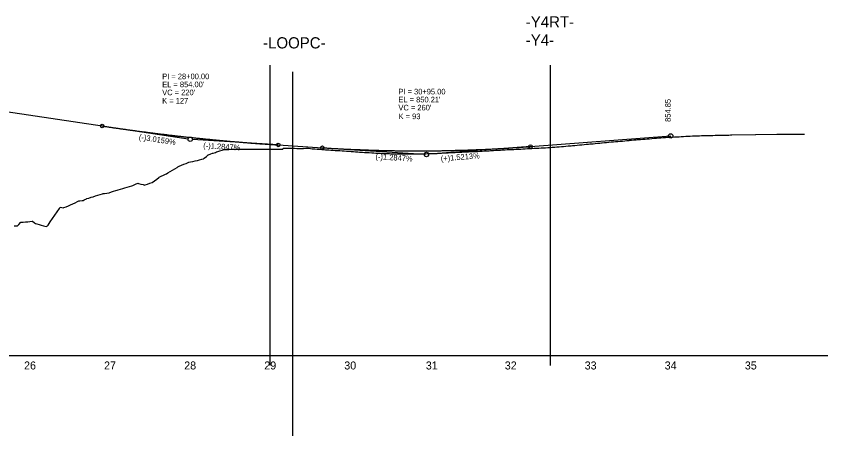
# Model space of a CAD drawing. Extents: x 570622 to 580296, y -55533 to -48575.
# Drawn here: x 575380 to 576394, y -53536 to -53012 of the extents above; entities that cross this region are included whole.
import ezdxf

# ---------------------------------------------------------------- set-up
doc = ezdxf.new("R2010")
doc.units = 0
for name, color, linetype in [('Default', 7, 'Continuous'), ('Exist Profile Cell', 7, 'Continuous'), ('Exist Vertical Profile Ground Line', 7, 'Continuous'), ('Exist Vertical Profile Horizontal Axis Label Major', 7, 'Continuous'), ('Prop Vertical Profile Curve Label', 7, 'Continuous'), ('Prop Vertical Profile Grade', 7, 'Continuous'), ('Prop Vertical Profile Grade Label', 7, 'Continuous'), ('Prop VPI Label', 7, 'Continuous')]:
    doc.layers.add(name, color=color, linetype=linetype)

msp = doc.modelspace()

# ---------------------------------------------------------------- linework, layer by layer
at = {"layer": 'Default'}
for p, q in [((575697.6, -53447.9), (575697.6, -53072.8)), ((576047.6, -53447.9), (576047.6, -53072.8)), ((575725.7, -53535.7), (575725.7, -53081.3)), ((576147.6, -53165.3), (576147.6, -53165.3)), ((576197.6, -53161.4), (576197.6, -53161.4)), ((576047.6, -53173.3), (576047.6, -53173.3)), ((576097.6, -53169.9), (576097.6, -53169.9)), ((575947.6, -53179.4), (575947.6, -53179.4)), ((575997.6, -53176.8), (575997.6, -53176.8))]:
    msp.add_line(p, q, dxfattribs=at)
at = {"layer": 'Exist Profile Cell'}
msp.add_line((573797.6, -53435.4), (576393.8, -53435.4), dxfattribs=at)
at = {"layer": 'Exist Vertical Profile Ground Line'}
for points in [[(576040.7, -53176.1), (576041.3, -53176), (576044.2, -53175.8), (576047, -53175.6), (576049.8, -53175.4), (576052.8, -53175.2), (576055.5, -53175), (576058.3, -53174.8), (576061.1, -53174.5), (576063.9, -53174.3), (576066.8, -53174), (576069.6, -53173.8), (576072.4, -53173.6), (576073.3, -53173.5), (576075.2, -53173.3), (576076.1, -53173.2), (576078.1, -53173), (576080.9, -53172.8), (576083.7, -53172.5), (576086.5, -53172.2), (576089.4, -53171.9), (576092.2, -53171.7), (576093.3, -53171.6), (576095, -53171.4), (576096.6, -53171.3), (576097.8, -53171.2), (576100.6, -53171), (576103.5, -53170.7), (576106.3, -53170.4), (576109.1, -53170.2), (576111.3, -53169.9), (576111.9, -53169.9), (576114.8, -53169.6), (576117.6, -53169.3), (576120.4, -53169), (576123.2, -53168.8), (576124.1, -53168.7), (576126.1, -53168.5), (576128.9, -53168.3), (576131.7, -53168.1), (576134.5, -53167.8), (576135.1, -53167.8), (576137.4, -53167.6), (576140.2, -53167.3), (576143, -53167), (576145.8, -53166.8), (576146.3, -53166.7), (576148.7, -53166.5), (576151.5, -53166.3), (576153, -53166.2), (576154.3, -53166.1), (576155.7, -53165.9), (576157.1, -53165.8), (576159.9, -53165.6), (576162.8, -53165.4), (576163.5, -53165.3), (576165.6, -53165.2), (576168.4, -53164.9), (576171.2, -53164.7), (576174.1, -53164.5), (576177.1, -53164.2), (576179.7, -53164), (576182.5, -53163.8), (576185.4, -53163.6), (576188.2, -53163.4), (576191, -53163.1), (576193.8, -53162.9), (576194.3, -53162.9), (576196.7, -53162.8), (576197.7, -53162.7), (576199.5, -53162.6), (576202.3, -53162.5), (576205.1, -53162.3), (576208, -53162.2), (576210.8, -53162), (576213.6, -53161.9), (576216.4, -53161.7), (576219.2, -53161.6), (576221.5, -53161.5), (576222.1, -53161.4), (576224.9, -53161.2), (576227, -53161.1), (576227.7, -53161.1), (576230.8, -53161), (576233.4, -53161), (576236.2, -53160.9), (576239, -53160.8), (576241.8, -53160.8), (576244.7, -53160.7), (576247.5, -53160.6), (576248.9, -53160.6), (576250.3, -53160.6), (576253.1, -53160.5), (576256, -53160.4), (576258.8, -53160.4), (576261.6, -53160.3), (576264.4, -53160.2), (576267.3, -53160.2), (576270.1, -53160.1), (576272.5, -53160), (576272.9, -53160)], [(576272.9, -53160), (576273.4, -53160), (576274, -53160), (576303.4, -53159.4), (576304.1, -53159.4), (576330.1, -53158.9), (576331.2, -53158.9), (576360.2, -53159.1), (576364.6, -53159.2)], [(575809.8, -53181.4), (575812.6, -53181.6), (575815.4, -53181.8), (575818.3, -53181.9), (575821.1, -53182.1), (575824.2, -53182.3), (575826.7, -53182.5), (575829.6, -53182.6), (575832.4, -53182.8), (575835.2, -53182.9), (575837.4, -53183), (575838, -53183.1), (575838.7, -53183.1), (575839.1, -53183.1), (575840.9, -53183.2), (575843.7, -53183.2), (575846.5, -53183.3), (575849.3, -53183.4), (575852.2, -53183.5), (575855, -53183.6), (575857.8, -53183.6), (575859.2, -53183.7), (575860.6, -53183.7), (575863.5, -53183.7), (575866.3, -53183.7), (575869.1, -53183.7), (575871.9, -53183.7), (575874.7, -53183.7), (575877.6, -53183.7), (575879.6, -53183.7), (575880.4, -53183.6), (575883.2, -53183.6), (575886, -53183.5), (575886.9, -53183.5), (575888.9, -53183.4), (575891.7, -53183.4), (575894.5, -53183.3), (575895.6, -53183.3), (575897.3, -53183.2), (575900.2, -53183.1), (575903, -53183), (575905.8, -53183), (575906.7, -53182.9), (575908.6, -53182.8), (575911.5, -53182.7), (575914.3, -53182.5), (575917.1, -53182.4), (575919, -53182.3), (575919.9, -53182.2), (575922.7, -53182.1), (575925.6, -53182), (575928.4, -53181.9), (575931.2, -53181.7), (575934, -53181.6), (575936.9, -53181.4), (575939.7, -53181.3), (575942.5, -53181.1), (575943.3, -53181.1), (575945.3, -53181), (575948.2, -53180.9), (575951, -53180.7), (575953.2, -53180.6), (575953.8, -53180.6), (575956.6, -53180.5), (575959.5, -53180.3), (575962.3, -53180.1), (575965.1, -53180), (575967.9, -53179.8), (575969.1, -53179.8), (575970.8, -53179.7), (575972.8, -53179.6), (575973.6, -53179.5), (575976.4, -53179.4), (575979.2, -53179.2), (575982, -53179), (575984.9, -53178.9), (575987.7, -53178.7), (575990.5, -53178.6), (575991.1, -53178.5), (575993.3, -53178.4), (575993.9, -53178.4), (575996.2, -53178.3), (575996.9, -53178.2), (575999, -53178.1), (576001.8, -53178), (576004.6, -53177.8), (576007.5, -53177.7), (576010.3, -53177.6), (576013.1, -53177.4), (576014.8, -53177.3), (576015.9, -53177.3), (576018.8, -53177.1), (576021.6, -53177), (576024.4, -53176.9), (576027.2, -53176.7), (576030.1, -53176.6), (576032.9, -53176.4), (576035.7, -53176.3), (576036.9, -53176.3), (576038.5, -53176.2), (576040.7, -53176.1)], [(575586.7, -53197.8), (575589.5, -53196.7), (575592.4, -53195.5), (575595.2, -53194.3), (575595.9, -53194), (575598, -53193.6), (575600.8, -53193.1), (575603.7, -53192.5), (575606.5, -53191.8), (575609.3, -53191.1), (575612.1, -53190.3), (575614.3, -53189.7), (575615, -53189.2), (575617.8, -53186.9), (575619.9, -53185), (575620.6, -53184.8), (575623.4, -53183.8), (575625.6, -53182.9), (575626.2, -53182.7), (575629.1, -53181.8), (575630.6, -53181.3), (575631.9, -53180.9), (575634.7, -53180), (575637.5, -53179.1), (575640.4, -53178.2), (575640.9, -53178), (575643.2, -53178), (575646, -53178), (575648.8, -53177.9), (575650.9, -53177.9), (575651.7, -53177.9), (575654.5, -53177.9), (575654.9, -53177.9), (575657.3, -53177.9), (575660.1, -53177.9), (575663, -53177.9), (575665.8, -53177.8), (575668.6, -53177.8), (575671.4, -53177.8), (575674.3, -53177.7), (575677.1, -53177.7), (575679.9, -53177.6), (575680.8, -53177.6), (575682.7, -53177.6), (575685.5, -53177.7), (575688.4, -53177.7), (575691.2, -53177.7), (575693.3, -53177.8), (575694, -53177.8), (575696.8, -53177.8), (575699.7, -53177.7), (575702.5, -53177.7), (575703.8, -53177.7), (575705.3, -53177.7), (575708.1, -53177.7), (575711, -53177.7), (575713.4, -53177.7), (575713.8, -53176.4), (575716.6, -53176.5), (575719.4, -53176.5), (575722.3, -53176.6), (575725.1, -53176.7), (575727.9, -53176.7), (575730.7, -53176.8), (575733.6, -53176.9), (575736.4, -53176.9), (575737.5, -53176.9), (575738, -53176.9), (575739.2, -53177), (575742, -53176.7), (575743.7, -53176.6), (575744.8, -53176.7), (575747.7, -53177), (575750, -53177.2), (575750.5, -53177.2), (575753.3, -53177.5), (575756.1, -53177.7), (575759, -53177.9), (575761.8, -53178.1), (575764.6, -53178.4), (575766.7, -53178.5), (575767.4, -53178.6), (575770.3, -53178.8), (575770.7, -53178.8), (575773.1, -53179), (575775.9, -53179.1), (575778.7, -53179.3), (575781.6, -53179.5), (575784.4, -53179.6), (575787.2, -53179.8), (575789.5, -53180), (575790, -53180), (575792.9, -53180.2), (575795.7, -53180.4), (575798.5, -53180.6), (575800.4, -53180.8), (575801.3, -53180.8), (575804.1, -53181), (575807, -53181.2), (575809, -53181.4), (575809.8, -53181.4)], [(575377.8, -53273.5), (575380.6, -53273.6), (575381.9, -53273.6), (575383.4, -53272), (575386.2, -53269), (575389, -53268.8), (575391.9, -53268.6), (575394.7, -53268.4), (575397.5, -53268.1), (575400.3, -53267.9), (575400.7, -53267.9), (575403.2, -53269.6), (575404.4, -53270.5), (575406, -53271), (575408.8, -53271.8), (575411.6, -53272.6), (575414.5, -53273.4), (575417.5, -53274.2), (575419.5, -53273.4), (575420.1, -53272.5), (575422.9, -53268.4), (575425.8, -53264.3), (575428.6, -53260.2), (575431.4, -53256), (575434.2, -53251.8), (575435.2, -53250.4), (575437.1, -53250.7), (575439.6, -53251), (575439.9, -53250.8), (575442.7, -53249.6), (575445.5, -53248.4), (575448.3, -53247.2), (575451.2, -53245.9), (575454, -53244.6), (575456.8, -53243.2), (575458.3, -53242.5), (575459.6, -53242.3), (575462.5, -53241.9), (575463.8, -53241.7), (575465.3, -53241), (575468.1, -53239.6), (575468.5, -53239.4), (575470.9, -53238.8), (575473.8, -53237.9), (575476.6, -53237.1), (575479.4, -53236.2), (575482.2, -53235.3), (575485.1, -53234.4), (575487.9, -53233.5), (575488.8, -53233.2), (575490.7, -53233), (575493.5, -53232.7), (575496.4, -53232.3), (575499.2, -53231.2), (575501.6, -53230.3), (575502, -53230.2), (575504.8, -53229.4), (575506.2, -53229), (575507.6, -53228.6), (575510.5, -53227.8), (575513.3, -53227), (575516.1, -53226.1), (575518.9, -53225.2), (575521.8, -53224.4), (575524.6, -53223.4), (575525.8, -53223), (575527.4, -53222.4), (575530.2, -53221.2), (575532.5, -53220.3), (575533.1, -53220.5), (575535.9, -53221.3), (575538.7, -53222.1), (575540.6, -53222.6), (575541.5, -53222.3), (575544.4, -53221.3), (575547.2, -53220.3), (575550, -53219.2), (575552.8, -53217.2), (575555.7, -53215.2), (575558.5, -53213.1), (575559, -53212.7), (575561.3, -53211.7), (575564.1, -53210.4), (575566.9, -53209.1), (575568.1, -53208.6), (575569.8, -53207.5), (575572.6, -53205.8), (575575.4, -53204.1), (575578.2, -53202.3), (575581.1, -53200.5), (575582.2, -53199.7), (575583.6, -53199), (575583.9, -53198.9), (575586.7, -53197.8)]]:
    msp.add_lwpolyline(points, dxfattribs=at)
at = {"layer": 'Prop Vertical Profile Curve Label'}
for centre in [(575487.6, -53148.8), (575707.6, -53172.5), (575762.6, -53176), (576022.6, -53174.5)]:
    msp.add_circle(centre, 2.25, dxfattribs=at)
at = {"layer": 'Prop Vertical Profile Grade'}
for p, q in [((575367.6, -53130.7), (575487.6, -53148.8)), ((576022.6, -53174.5), (576197.6, -53161.2)), ((575707.6, -53172.5), (575762.6, -53176))]:
    msp.add_line(p, q, dxfattribs=at)
for points in [[(575487.6, -53148.8), (575492, -53149.5), (575496.4, -53150.1), (575500.8, -53150.8), (575505.2, -53151.4), (575509.6, -53152.1), (575514, -53152.7), (575518.4, -53153.3), (575522.8, -53153.9), (575527.2, -53154.5), (575531.6, -53155.1), (575536, -53155.7), (575540.4, -53156.2), (575544.8, -53156.8), (575549.2, -53157.4), (575553.6, -53157.9), (575558, -53158.5), (575562.4, -53159), (575566.8, -53159.5), (575571.2, -53160.1), (575575.6, -53160.6), (575580, -53161.1), (575584.4, -53161.6), (575588.8, -53162.1), (575593.2, -53162.6), (575597.6, -53163), (575602, -53163.5), (575606.4, -53164), (575610.8, -53164.4), (575615.2, -53164.9), (575619.6, -53165.3), (575624, -53165.7), (575628.4, -53166.2), (575632.8, -53166.6), (575637.2, -53167), (575641.6, -53167.4), (575646, -53167.8), (575650.4, -53168.2), (575654.8, -53168.5), (575659.2, -53168.9), (575663.6, -53169.3), (575668, -53169.6), (575672.4, -53170), (575676.8, -53170.3), (575681.2, -53170.7), (575685.6, -53171), (575690, -53171.3), (575694.4, -53171.6), (575698.8, -53171.9), (575703.2, -53172.2), (575707.6, -53172.5)], [(575762.6, -53176), (575767.8, -53176.3), (575773, -53176.7), (575778.2, -53177), (575783.4, -53177.2), (575788.6, -53177.5), (575793.8, -53177.8), (575799, -53178), (575804.2, -53178.2), (575809.4, -53178.4), (575814.6, -53178.6), (575819.8, -53178.8), (575825, -53179), (575830.2, -53179.1), (575835.4, -53179.3), (575840.6, -53179.4), (575845.8, -53179.5), (575851, -53179.6), (575856.2, -53179.7), (575861.4, -53179.7), (575866.6, -53179.8), (575871.8, -53179.8), (575877, -53179.8), (575882.2, -53179.8), (575887.4, -53179.8), (575892.6, -53179.8), (575897.8, -53179.8), (575903, -53179.7), (575908.2, -53179.7), (575913.4, -53179.6), (575918.6, -53179.5), (575923.8, -53179.4), (575929, -53179.2), (575934.2, -53179.1), (575939.4, -53178.9), (575944.6, -53178.8), (575949.8, -53178.6), (575955, -53178.4), (575960.2, -53178.2), (575965.4, -53178), (575970.6, -53177.7), (575975.8, -53177.5), (575981, -53177.2), (575986.2, -53176.9), (575991.4, -53176.6), (575996.6, -53176.3), (576001.8, -53175.9), (576007, -53175.6), (576012.2, -53175.2), (576017.4, -53174.9), (576022.6, -53174.5)]]:
    msp.add_spline(points, degree=3, dxfattribs=at)
at = {"layer": 'Prop VPI Label'}
for p, q in [((575487.6, -53148.8), (575594.9, -53165)), ((575707.6, -53172.5), (575600.4, -53165.6)), ((575762.6, -53176), (575889.9, -53184.2)), ((576022.6, -53174.5), (575895.4, -53184.2))]:
    msp.add_line(p, q, dxfattribs=at)
for centre in [(575597.6, -53165.4), (576197.6, -53161.2), (575892.6, -53184.4)]:
    msp.add_circle(centre, 2.75, dxfattribs=at)

# ---------------------------------------------------------------- texts
at = {"layer": 'Exist Profile Cell'}
for s, p in [('-Y4RT-', (576016.7, -53025.8)), ('-LOOPC-', (575688.6, -53052)), ('-Y4-', (576016.7, -53048.5))]:
    msp.add_text(s, height=14, dxfattribs=at).set_placement(p)
at = {"layer": 'Exist Vertical Profile Horizontal Axis Label Major'}
for s, p in [('26', (575390.1, -53452.9)), ('27', (575490, -53452.9)), ('28', (575590.1, -53452.9)), ('29', (575690.1, -53452.9)), ('30', (575790, -53452.9)), ('31', (575891.8, -53452.9)), ('32', (575990.4, -53452.9)), ('33', (576090.2, -53452.9)), ('34', (576190.1, -53452.9)), ('35', (576290.2, -53452.9))]:
    msp.add_text(s, height=10, dxfattribs=at).set_placement(p)
at = {"layer": 'Prop Vertical Profile Curve Label'}
for s, p in [("VC = 220'", (575562.6, -53110.4)), ('K = 127', (575562.6, -53120.8)), ("VC = 260'", (575857.6, -53129.4)), ('K = 93', (575857.8, -53140.3))]:
    msp.add_text(s, height=7, dxfattribs=at).set_placement(p)
at = {"layer": 'Prop Vertical Profile Grade Label'}
for s, rotation, p in [('(-)3.0159%', 351.4247, (575533.1, -53165.8)), ('(-)1.2847%', 356.3245, (575613.7, -53176.5)), ('(-)1.2847%', 356.3245, (575828.8, -53190.3)), ('(+)1.5213%', 4.3499, (575910.8, -53193))]:
    msp.add_text(s, height=7, rotation=rotation, dxfattribs=at).set_placement(p)
at = {"layer": 'Prop VPI Label'}
for s, p in [('PI = 28+00.00', (575562.6, -53090.4)), ("EL = 854.00'", (575562.6, -53100.4)), ('PI = 30+95.00', (575857.6, -53109.4)), ("EL = 850.21'", (575857.6, -53119.4))]:
    msp.add_text(s, height=7, dxfattribs=at).set_placement(p)
msp.add_text('854.85', height=7, rotation=90, dxfattribs=at).set_placement((576197.6, -53143.7))

doc.saveas('drawing.dxf')
